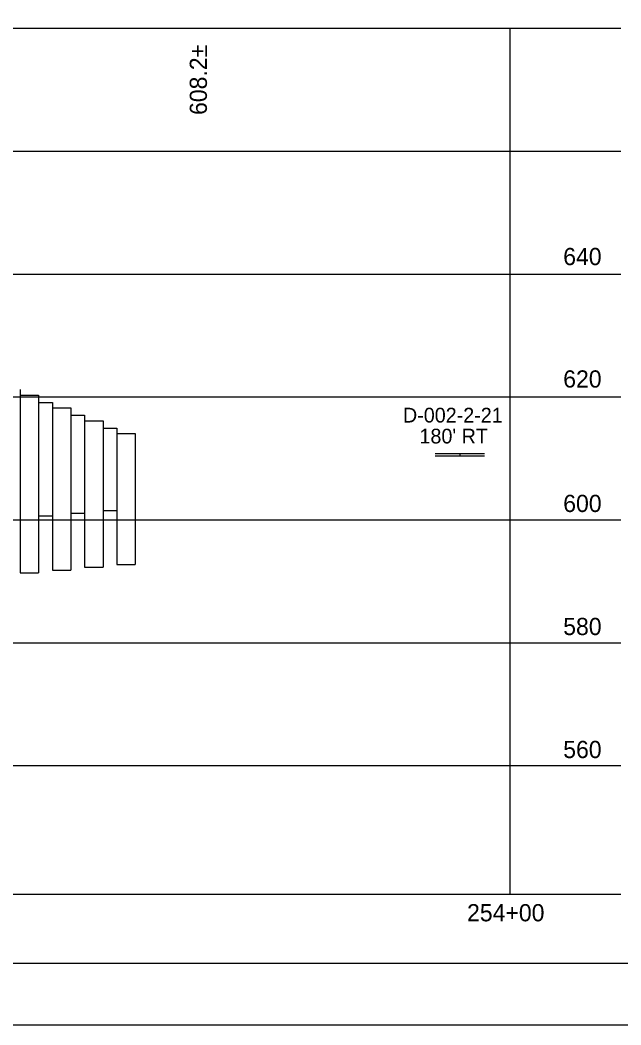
# Model space of a CAD drawing. Extents: x -2280229 to 1306, y -58886 to 440.
# Drawn here: x 505.2 to 603, y 0 to 163.6 of the extents above; entities that cross this region are included whole.
import ezdxf

# ---------------------------------------------------------------- set-up
doc = ezdxf.new("R2010")
doc.units = 0
for name, color, linetype in [('BR_P_Sub_Deep_Object', 7, 'Continuous'), ('GT_Project_Text', 7, 'Continuous'), ('SC_Scratch1', 7, 'Continuous'), ('SC_Scratch2', 7, 'Continuous'), ('SC_Scratch3', 7, 'Continuous'), ('SC_Scratch5', 7, 'Continuous'), ('SC_Scratch6', 7, 'Continuous'), ('SC_Scratch9', 7, 'Continuous'), ('SH_Minor_Grid_Line', 7, 'Continuous')]:
    doc.layers.add(name, color=color, linetype=linetype)

msp = doc.modelspace()

# ---------------------------------------------------------------- linework, layer by layer
at = {"layer": 'BR_P_Sub_Deep_Object'}
for p, q in [((505.23, 103.4), (505.23, 73.6)), ((505.23, 102.51), (508.23, 102.51)), ((508.23, 102.51), (508.23, 73.6)), ((508.23, 101.32), (510.48, 101.32)), ((510.48, 101.32), (510.48, 74.04)), ((510.48, 100.42), (513.48, 100.42)), ((513.48, 100.42), (513.48, 74.04)), ((513.48, 99.23), (515.73, 99.23)), ((515.73, 99.23), (515.73, 74.48)), ((515.73, 98.34), (518.73, 98.34)), ((518.73, 98.34), (518.73, 74.48)), ((518.73, 97.15), (520.98, 97.15)), ((520.98, 97.15), (520.98, 74.92)), ((520.98, 96.26), (523.98, 96.26)), ((523.98, 96.26), (523.98, 74.92)), ((518.73, 83.73), (520.98, 83.73)), ((508.23, 82.85), (510.48, 82.85)), ((513.48, 83.29), (515.73, 83.29)), ((505.23, 73.6), (508.23, 73.6)), ((510.48, 74.04), (513.48, 74.04)), ((515.73, 74.48), (518.73, 74.48)), ((520.98, 74.92), (523.98, 74.92))]:
    msp.add_line(p, q, dxfattribs=at)
at = {"layer": 'GT_Project_Text'}
msp.add_lwpolyline([(0, 0), (680, 0), (680, 440), (0, 440)], close=True, dxfattribs=at)
at = {"layer": 'SC_Scratch1'}
msp.add_lwpolyline([(30, 430), (670, 430), (670, 10), (30, 10)], close=True, dxfattribs=at)
at = {"layer": 'SC_Scratch2'}
for p, q in [((572.8, 93.01), (580.8, 93.01)), ((572.8, 92.61), (580.8, 92.61)), ((576.8, 93.01), (576.8, 92.61))]:
    msp.add_line(p, q, dxfattribs=at)
at = {"layer": 'SC_Scratch5'}
for p, q in [((603.01, 162.21), (45.43, 162.21)), ((603.01, 21.22), (45.43, 21.22))]:
    msp.add_line(p, q, dxfattribs=at)
at = {"layer": 'SC_Scratch6'}
msp.add_line((576.8, 93.01), (576.8, 92.61), dxfattribs=at)
at = {"layer": 'SH_Minor_Grid_Line'}
for p, q in [((584.98, 21.22), (584.98, 162.21)), ((45.43, 142.21), (603.01, 142.21)), ((45.43, 122.21), (603.01, 122.21)), ((45.43, 102.21), (603.01, 102.21)), ((45.43, 82.21), (603.01, 82.21)), ((45.43, 62.21), (603.01, 62.21)), ((45.43, 42.21), (603.01, 42.21))]:
    msp.add_line(p, q, dxfattribs=at)

# ---------------------------------------------------------------- texts
at = {"layer": 'SC_Scratch3'}
for s, p in [('D-002-2-21', (567.54, 98.05)), ("180' RT", (570.23, 94.64))]:
    msp.add_text(s, height=2.4, dxfattribs=at).set_placement(p)
at = {"layer": 'SC_Scratch9'}
msp.add_text('608.2±', height=2.8, rotation=90, dxfattribs=at).set_placement((535.64, 148.11))
for s, p in [('640', (593.62, 123.67)), ('620', (593.62, 103.74)), ('600', (593.62, 83.48)), ('580', (593.62, 63.45)), ('560', (593.62, 43.43)), ('254+00', (577.97, 16.86))]:
    msp.add_text(s, height=2.8, dxfattribs=at).set_placement(p)

doc.saveas('drawing.dxf')
